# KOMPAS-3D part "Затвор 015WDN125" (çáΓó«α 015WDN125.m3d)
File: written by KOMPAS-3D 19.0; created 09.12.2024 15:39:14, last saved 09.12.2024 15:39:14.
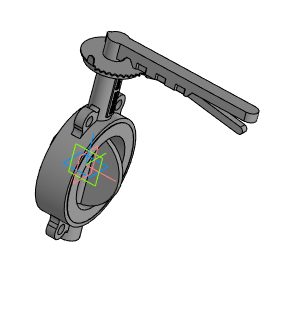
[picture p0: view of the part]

Document properties: Автор: Евгений; Полное имя файла: ..\Затвор 015WDN125.a3d

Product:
- Part/product: Затвор 015WDN125
    Масса: 17.9904

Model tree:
1. Операция без истории:1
